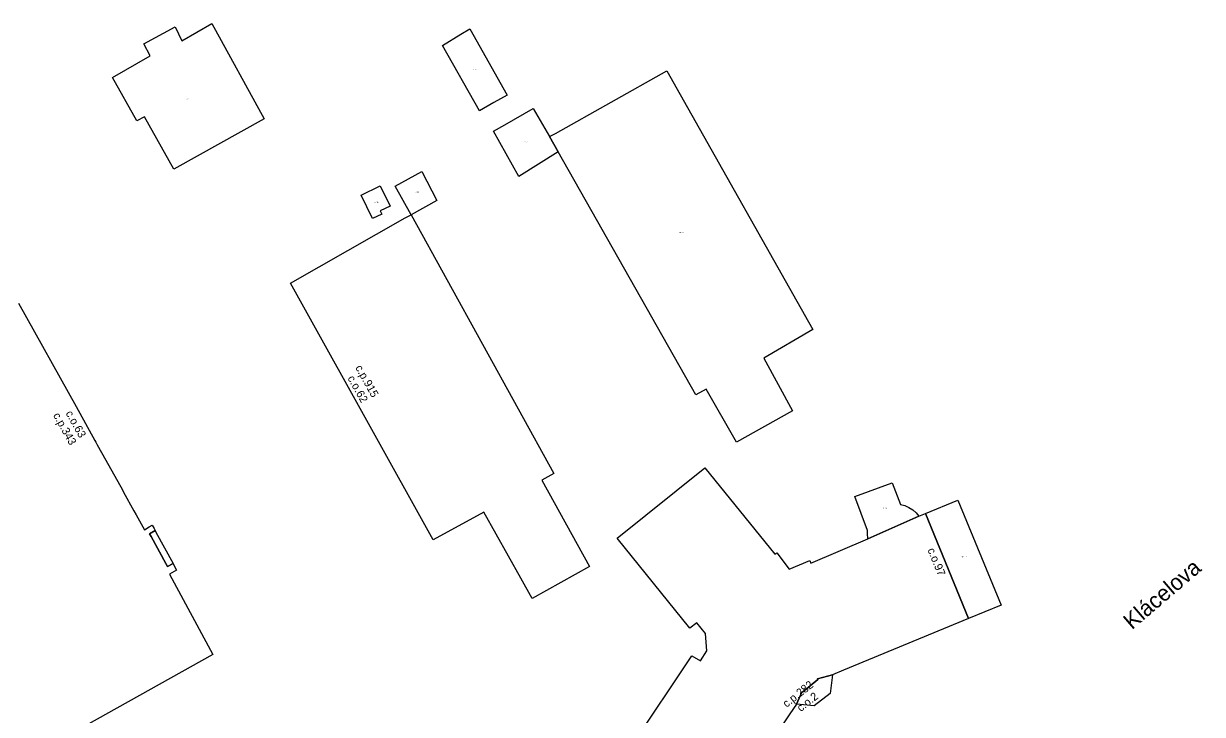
# Model space of a CAD drawing. Extents: x -600391 to -599491, y -1160176 to -1159402.
# Drawn here: x -600035.9 to -599888.6, y -1159910.3 to -1159824 of the extents above; entities that cross this region are included whole.
import ezdxf

# ---------------------------------------------------------------- set-up
doc = ezdxf.new("R2010")
doc.units = 0
for name, color, linetype in [('Level 10', 7, 'Continuous'), ('Level 11', 7, 'Continuous'), ('Level 12', 7, 'Continuous'), ('Level 24', 7, 'Continuous'), ('Level 25', 7, 'Continuous'), ('Level 61', 7, 'Continuous'), ('Level 62', 7, 'Continuous')]:
    doc.layers.add(name, color=color, linetype=linetype)

msp = doc.modelspace()

# ---------------------------------------------------------------- linework, layer by layer
at = {"layer": 'Level 61'}
for points in [[(-600020.88, -1159826.57), (-600016.97, -1159824.42)], [(-600016.97, -1159824.42), (-600016.11, -1159826.18)], [(-600016.11, -1159826.18), (-600012.4, -1159824.03)], [(-600012.4, -1159824.03), (-600005.86, -1159835.91)], [(-599983.58, -1159826.76), (-599981.27, -1159825.37)], [(-599981.27, -1159825.37), (-599980.14, -1159824.7)], [(-599980.14, -1159824.7), (-599975.49, -1159832.96)], [(-600020.07, -1159828.08), (-600020.88, -1159826.57)], [(-599978.93, -1159834.94), (-599983.58, -1159826.76)], [(-600024.8, -1159830.75), (-600020.07, -1159828.08)], [(-600021.75, -1159836.17), (-600024.8, -1159830.75)], [(-599969.46, -1159837.75), (-599955.55, -1159829.92)], [(-599955.55, -1159829.92), (-599955.01, -1159830.88)], [(-599955.01, -1159830.88), (-599954.42, -1159831.92)], [(-599954.42, -1159831.92), (-599937.3, -1159862.24)], [(-599977.13, -1159833.9), (-599978.93, -1159834.94)], [(-599975.49, -1159832.96), (-599977.13, -1159833.9)], [(-599975.76, -1159836.66), (-599972.22, -1159834.65)], [(-599972.22, -1159834.65), (-599970.19, -1159838.15)], [(-600020.8, -1159835.7), (-600021.75, -1159836.17)], [(-600017.14, -1159842.2), (-600020.8, -1159835.7)], [(-600005.86, -1159835.91), (-600017.14, -1159842.2)], [(-599977.17, -1159837.46), (-599975.76, -1159836.66)], [(-599974.03, -1159843.12), (-599977.17, -1159837.46)], [(-599970.19, -1159838.15), (-599969.46, -1159837.75)], [(-599970.19, -1159838.15), (-599969.1, -1159840.07)], [(-599969.1, -1159840.07), (-599970.19, -1159838.15)], [(-599969.1, -1159840.07), (-599974.03, -1159843.12)], [(-599951.91, -1159870.4), (-599969.1, -1159840.07)], [(-599989.47, -1159844.35), (-599986.14, -1159842.5)], [(-599986.14, -1159842.5), (-599984.28, -1159846.14)], [(-599993.71, -1159845.46), (-599991.33, -1159844.32)], [(-599991.33, -1159844.32), (-599990.11, -1159846.85)], [(-599987.48, -1159847.92), (-599989.47, -1159844.35)], [(-599992.31, -1159848.38), (-599993.71, -1159845.46)], [(-599990.11, -1159846.85), (-599991.34, -1159847.44)], [(-599991.34, -1159847.44), (-599991.15, -1159847.83)], [(-599984.28, -1159846.14), (-599987.48, -1159847.92)], [(-600002.57, -1159856.45), (-599988.21, -1159848.31)], [(-599991.15, -1159847.83), (-599992.31, -1159848.38)], [(-599988.21, -1159848.31), (-599987.48, -1159847.92)], [(-599987.48, -1159847.92), (-599969.64, -1159880.25)], [(-600000.68, -1159859.83), (-600002.57, -1159856.45)], [(-600036.54, -1159858.98), (-600029.35, -1159871.89)], [(-599984.71, -1159888.53), (-600000.68, -1159859.83)], [(-599937.3, -1159862.24), (-599943.43, -1159865.82)], [(-599943.43, -1159865.82), (-599939.83, -1159872.43)], [(-599950.61, -1159869.69), (-599951.91, -1159870.4)], [(-599946.83, -1159876.34), (-599950.61, -1159869.69)], [(-600029.35, -1159871.89), (-600026.99, -1159876.13)], [(-599939.83, -1159872.43), (-599946.83, -1159876.34)], [(-600026.99, -1159876.13), (-600026.87, -1159876.34)], [(-600026.87, -1159876.34), (-600026.71, -1159876.64)], [(-600026.71, -1159876.64), (-600025.63, -1159878.57)], [(-600025.63, -1159878.57), (-600023.56, -1159882.3)], [(-599961.76, -1159888.32), (-599950.79, -1159879.55)], [(-599950.79, -1159879.55), (-599942.06, -1159890.32)], [(-599969.64, -1159880.25), (-599971.16, -1159881.07)], [(-599971.16, -1159881.07), (-599965.19, -1159891.85)], [(-600023.56, -1159882.3), (-600023.41, -1159882.56)], [(-600023.41, -1159882.56), (-600022.12, -1159884.89)], [(-599932.04, -1159883.12), (-599927.37, -1159881.39)], [(-599927.37, -1159881.39), (-599926.33, -1159884.12)], [(-599930.45, -1159887.37), (-599932.04, -1159883.12)], [(-599926.33, -1159884.12), (-599925.81, -1159884.25)], [(-599925.81, -1159884.25), (-599925.3, -1159884.47)], [(-599923.23, -1159885.24), (-599919.16, -1159883.57)], [(-599919.16, -1159883.57), (-599913.77, -1159896.69)], [(-600022.12, -1159884.89), (-600021.83, -1159885.41)], [(-600021.83, -1159885.41), (-600020.8, -1159887.27)], [(-599978.39, -1159885.08), (-599984.71, -1159888.53)], [(-599973.76, -1159893.33), (-599978.39, -1159885.08)], [(-599930.41, -1159888.39), (-599924.05, -1159885.57)], [(-599924.05, -1159885.57), (-599930.41, -1159888.39)], [(-599925.3, -1159884.47), (-599924.82, -1159884.77)], [(-599924.82, -1159884.77), (-599924.4, -1159885.14)], [(-599924.4, -1159885.14), (-599924.05, -1159885.57)], [(-599924.05, -1159885.57), (-599923.23, -1159885.24)], [(-599923.23, -1159885.24), (-599917.84, -1159898.37)], [(-599917.84, -1159898.37), (-599923.23, -1159885.24)], [(-600020.8, -1159887.27), (-600020.19, -1159886.91)], [(-600020.19, -1159886.91), (-600019.82, -1159886.7)], [(-600019.82, -1159886.7), (-600019.6, -1159887.11)], [(-600019.6, -1159887.11), (-600019.45, -1159887.38)], [(-600019.45, -1159887.38), (-600020.16, -1159887.77)], [(-600020.16, -1159887.77), (-600019.45, -1159887.38)], [(-600020.16, -1159887.77), (-600019.97, -1159888.11)], [(-600019.97, -1159888.11), (-600020.16, -1159887.77)], [(-600019.97, -1159888.11), (-600018.12, -1159891.49)], [(-600018.12, -1159891.49), (-600019.97, -1159888.11)], [(-600019.45, -1159887.38), (-600019.36, -1159887.55)], [(-600019.36, -1159887.55), (-600017.23, -1159891.5)], [(-599952.65, -1159899.58), (-599961.76, -1159888.32)], [(-599937.55, -1159891.43), (-599930.41, -1159888.39)], [(-599930.48, -1159887.74), (-599930.45, -1159887.37)], [(-599930.41, -1159888.39), (-599930.48, -1159887.74)], [(-599942.06, -1159890.32), (-599941.8, -1159890.17)], [(-599941.8, -1159890.17), (-599940.26, -1159892.19)], [(-600018.12, -1159891.49), (-600017.91, -1159891.87)], [(-600017.91, -1159891.87), (-600018.12, -1159891.49)], [(-600017.91, -1159891.87), (-600017.23, -1159891.5)], [(-600017.23, -1159891.5), (-600017.91, -1159891.87)], [(-600017.23, -1159891.5), (-600017.09, -1159891.77)], [(-599940.26, -1159892.19), (-599937.67, -1159891.12)], [(-599937.67, -1159891.12), (-599937.55, -1159891.43)], [(-600016.79, -1159892.32), (-600017.69, -1159892.83)], [(-600017.69, -1159892.83), (-600012.26, -1159902.87)], [(-600017.09, -1159891.77), (-600016.79, -1159892.32)], [(-599965.19, -1159891.85), (-599972.37, -1159895.85)], [(-599972.37, -1159895.85), (-599973.76, -1159893.33)], [(-599913.77, -1159896.69), (-599917.84, -1159898.37)], [(-599951.8, -1159898.9), (-599952.65, -1159899.58)], [(-599950.7, -1159900.21), (-599951.8, -1159898.9)], [(-599917.84, -1159898.37), (-599933.46, -1159904.8)], [(-599950.53, -1159902.39), (-599950.7, -1159900.21)], [(-600012.26, -1159902.87), (-600028.13, -1159911.71)], [(-599959.88, -1159914.2), (-599952.41, -1159903.03)], [(-599952.41, -1159903.03), (-599951.32, -1159903.66)], [(-599951.32, -1159903.66), (-599950.53, -1159902.39)], [(-599933.46, -1159904.8), (-599934.82, -1159905.39)], [(-599936.65, -1159905.97), (-599938.57, -1159907.58)], [(-599938.57, -1159907.58), (-599936.65, -1159905.97)], [(-599934.82, -1159905.39), (-599936.72, -1159905.88)], [(-599936.72, -1159905.88), (-599934.82, -1159905.39)], [(-599936.72, -1159905.88), (-599936.65, -1159905.97)], [(-599936.65, -1159905.97), (-599936.72, -1159905.88)], [(-599934.82, -1159905.39), (-599935.14, -1159907.72)], [(-599938.64, -1159907.49), (-599939.33, -1159909.04)], [(-599939.33, -1159909.04), (-599938.64, -1159907.49)], [(-599938.57, -1159907.58), (-599938.64, -1159907.49)], [(-599938.64, -1159907.49), (-599938.57, -1159907.58)], [(-599935.14, -1159907.72), (-599937.13, -1159909.28)], [(-599939.33, -1159909.04), (-599940.17, -1159910.25)], [(-599937.13, -1159909.28), (-599939.33, -1159909.04)], [(-599940.17, -1159910.25), (-599952.05, -1159927.96)]]:
    msp.add_lwpolyline(points, dxfattribs=at)
at = {"layer": 'Level 62'}
for points in [[(-600021.75, -1159836.17), (-600024.8, -1159830.75), (-600020.07, -1159828.08), (-600020.88, -1159826.57), (-600016.97, -1159824.42), (-600016.11, -1159826.18), (-600012.4, -1159824.03), (-600005.86, -1159835.91), (-600017.14, -1159842.2), (-600020.8, -1159835.7), (-600021.75, -1159836.17)], [(-599977.13, -1159833.9), (-599978.93, -1159834.94), (-599983.58, -1159826.76), (-599981.27, -1159825.37), (-599980.14, -1159824.7), (-599975.49, -1159832.96), (-599977.13, -1159833.9)], [(-599955.01, -1159830.88), (-599954.42, -1159831.92), (-599937.3, -1159862.24), (-599943.43, -1159865.82), (-599939.83, -1159872.43), (-599946.83, -1159876.34), (-599950.61, -1159869.69), (-599951.91, -1159870.4), (-599969.1, -1159840.07), (-599970.19, -1159838.15), (-599969.46, -1159837.75), (-599955.55, -1159829.92), (-599955.01, -1159830.88)], [(-599975.76, -1159836.66), (-599972.22, -1159834.65), (-599970.19, -1159838.15), (-599969.1, -1159840.07), (-599974.03, -1159843.12), (-599977.17, -1159837.46), (-599975.76, -1159836.66)], [(-599987.48, -1159847.92), (-599989.47, -1159844.35), (-599986.14, -1159842.5), (-599984.28, -1159846.14), (-599987.48, -1159847.92)], [(-599991.34, -1159847.44), (-599991.15, -1159847.83), (-599992.31, -1159848.38), (-599993.71, -1159845.46), (-599991.33, -1159844.32), (-599990.11, -1159846.85), (-599991.34, -1159847.44)], [(-599965.19, -1159891.85), (-599972.37, -1159895.85), (-599973.76, -1159893.33), (-599978.39, -1159885.08), (-599984.71, -1159888.53), (-600000.68, -1159859.83), (-600002.57, -1159856.45), (-599988.21, -1159848.31), (-599987.48, -1159847.92), (-599969.64, -1159880.25), (-599971.16, -1159881.07), (-599965.19, -1159891.85)], [(-600036.54, -1159858.98), (-600029.35, -1159871.89), (-600026.99, -1159876.13), (-600026.87, -1159876.34)], [(-600026.87, -1159876.34), (-600026.71, -1159876.64), (-600025.63, -1159878.57), (-600023.56, -1159882.3), (-600023.41, -1159882.56), (-600022.12, -1159884.89), (-600021.83, -1159885.41), (-600020.8, -1159887.27), (-600020.19, -1159886.91), (-600019.82, -1159886.7), (-600019.6, -1159887.11), (-600019.45, -1159887.38), (-600020.16, -1159887.77), (-600019.97, -1159888.11), (-600018.12, -1159891.49), (-600017.91, -1159891.87), (-600017.23, -1159891.5), (-600017.09, -1159891.77), (-600016.79, -1159892.32), (-600017.69, -1159892.83), (-600012.26, -1159902.87), (-600028.13, -1159911.71)], [(-599959.88, -1159914.2), (-599952.41, -1159903.03), (-599951.32, -1159903.66), (-599950.53, -1159902.39), (-599950.7, -1159900.21), (-599951.8, -1159898.9), (-599952.65, -1159899.58), (-599961.76, -1159888.32), (-599950.79, -1159879.55), (-599942.06, -1159890.32), (-599941.8, -1159890.17), (-599940.26, -1159892.19), (-599937.67, -1159891.12), (-599937.55, -1159891.43), (-599930.41, -1159888.39), (-599924.05, -1159885.57), (-599923.23, -1159885.24), (-599917.84, -1159898.37), (-599933.46, -1159904.8), (-599934.82, -1159905.39), (-599936.72, -1159905.88), (-599936.65, -1159905.97), (-599938.57, -1159907.58), (-599938.64, -1159907.49), (-599939.33, -1159909.04)], [(-599924.05, -1159885.57), (-599930.41, -1159888.39), (-599930.48, -1159887.74), (-599930.45, -1159887.37), (-599932.04, -1159883.12), (-599927.37, -1159881.39), (-599926.33, -1159884.12), (-599925.81, -1159884.25), (-599925.3, -1159884.47), (-599924.82, -1159884.77), (-599924.4, -1159885.14), (-599924.05, -1159885.57)], [(-599919.16, -1159883.57), (-599913.77, -1159896.69), (-599917.84, -1159898.37), (-599923.23, -1159885.24), (-599919.16, -1159883.57)], [(-600017.23, -1159891.5), (-600017.91, -1159891.87), (-600018.12, -1159891.49), (-600019.97, -1159888.11), (-600020.16, -1159887.77), (-600019.45, -1159887.38), (-600019.36, -1159887.55), (-600017.23, -1159891.5)], [(-599934.82, -1159905.39), (-599935.14, -1159907.72), (-599937.13, -1159909.28), (-599939.33, -1159909.04), (-599938.64, -1159907.49), (-599938.57, -1159907.58), (-599936.65, -1159905.97), (-599936.72, -1159905.88), (-599934.82, -1159905.39)], [(-599939.33, -1159909.04), (-599940.17, -1159910.25), (-599952.05, -1159927.96)]]:
    msp.add_lwpolyline(points, dxfattribs=at)

# ---------------------------------------------------------------- texts
at = {"layer": 'Level 10'}
for s, rotation, p in [('c.o.62', 299.0924, (-599995.46, -1159868.33)), ('c.o.63', 299.1153, (-600030.68, -1159872.71)), ('c.o.97', 292.3334, (-599922.99, -1159889.78)), ('c.o.2', 38.0916, (-599938.81, -1159910.06))]:
    msp.add_text(s, height=1, rotation=rotation, dxfattribs=at).set_placement(p)
at = {"layer": 'Level 11'}
msp.add_text('Klácelova', height=2, rotation=40.5315, dxfattribs=at).set_placement((-599897.43, -1159899.83))
at = {"layer": 'Level 12'}
for s, rotation, p in [('c.p.915', 299.0924, (-599994.49, -1159867.01)), ('c.p.343', 299.1153, (-600032.25, -1159872.97)), ('c.p.282', 38.0916, (-599940.58, -1159909.53))]:
    msp.add_text(s, height=1, rotation=rotation, dxfattribs=at).set_placement(p)
at = {"layer": 'Level 24'}
for s, p in [('c.z.203', (-599979.78, -1159829.83)), ('c.z.224', (-600015.66, -1159833.53)), ('c.z.202', (-599973.32, -1159838.88)), ('c.z.315', (-599986.92, -1159845.1)), ('c.z.250', (-599992.03, -1159846.4)), ('c.z.190', (-599928.48, -1159884.59))]:
    msp.add_text(s, height=0.1, dxfattribs=at).set_placement(p)
at = {"layer": 'Level 25'}
for s, p in [('c.pp.915_A', (-599954.07, -1159850.15)), ('c.pp.282_A', (-599918.76, -1159890.68))]:
    msp.add_text(s, height=0.1, dxfattribs=at).set_placement(p)

doc.saveas('drawing.dxf')
